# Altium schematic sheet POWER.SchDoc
size A4
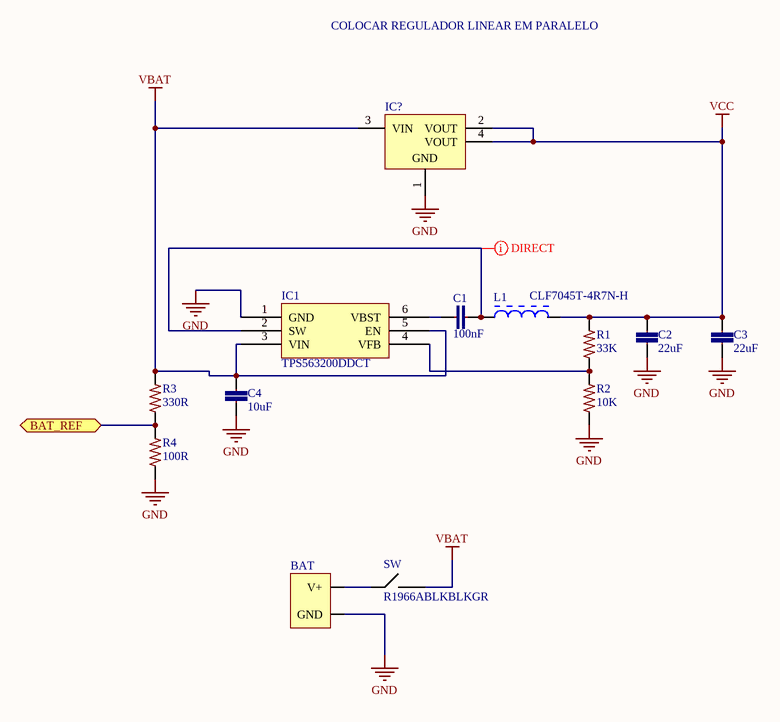
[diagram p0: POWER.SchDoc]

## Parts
BAT  XT60  [BATTERY_CONECTO-PCB]  (value not drawn)
C1  100nF  [0402-CAP]
C2  22uF  [1206-CAP]
C3  22uF  [1206-CAP]
C4  10uF  [1210-CAP]
IC1  TPS563200DDCT  [SOT95P280X110-6N]
IC?  LD1117S33CTR  [SOT-223_N]  (value not drawn)
L1  CLF7045T-4R7N-H  [CLF7045T]
R1  33K  [0402-RES-HD]
R2  10K  [0402-RES-HD]
R3  330R  [0402-RES-HD]
R4  100R  [0402-RES-HD]
SW  R1966ABLKBLKGR  [R1966AB-PCB]

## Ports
BAT_REF

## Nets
GND: BAT.1(GND) C2.1 C3.1 C4.1 IC1.1(GND) IC?.1(GND) R2.1 R4.1
VBAT: C4.2 IC1.3(VIN) IC1.5(EN) IC?.3(VIN) R3.2 SW.1
VCC: C2.2 C3.2 IC?.2(VOUT) IC?.4(VOUT) L1.2 R1.2
BAT_REF: R3.1 R4.2 ; port BAT_REF
NetBAT_0: BAT.0(V+) SW.0
NetC1_1: C1.1 IC1.6(VBST)
NetC1_2: C1.2 IC1.2(SW) L1.1
NetIC1_4: IC1.4(VFB) R1.1 R2.2

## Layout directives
net class DIRECT: NetC1_2

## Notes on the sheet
- COLOCAR REGULADOR LINEAR EM PARALELO

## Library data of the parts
BAT = BATTERY_CONNECTOR: XT60 PRT-10474
C1 = CC0402-100nF-50v-A.3: CAP CER 0.1UF 50V 10% X7R 0402; Part No: C1005X7R1H104K050BB; Value: 100n; Cod EMS: 05.281.019.021
C2 C3 = CC1206-22uF-6.3V-1: CAP CER 22UF 6.3V 20% X5R 1206; Part No: C3216X5R0J226M085AC; Value: 22u; Rule: UNIONINDEX{}0[]RULEKIND{}PolygonConnect[]NETSCOPE{}AnyNet[]LAYERKIND{}SameLayer[]NAME{}Schematic Polygon Connect Style[]CONNECTSTYLE{}Direct[]RELIEFCONDUCTORWIDTH{}10mil[]RELIEFENTRIES{}4[]POLYGONRELIEFANGLE{}45 Angle[]AIRGAPWIDTH{}10mil[]UNIT{}Imperial[]PcbType{}ProtelPcb
C4 = CC1210-10uF-6: CAP CER 10UF 50V 20% X5R 1210; Part No: UMK325BJ106MM; value: 10u; Cod EMS: 05.281.019.522
IC1 = TPS563200DDCT-01.A.2: IC REG BUCK ADJ 3A SYNC 6SOT
IC? = CMP-0244-00307-1: Fixed Low Drop Positive Voltage Regulator, 3.3V, 4-Pin SOT-223, Tape and Reel
L1 = CLF7045T-4R7N-H-2: FIXED IND 4.7UH 4.1A 20 MOHM SMD; Family Description: INDUTORES FIXOS 7,2x6,9mm TDK CLF7045T -45 A 125oC; Rule: UNIONINDEX{}0[]RULEKIND{}PolygonConnect[]NETSCOPE{}AnyNet[]LAYERKIND{}SameLayer[]NAME{}Schematic Polygon Connect Style[]CONNECTSTYLE{}Direct[]RELIEFCONDUCTORWIDTH{}10mil[]RELIEFENTRIES{}4[]POLYGONRELIEFANGLE{}45 Angle[]AIRGAPWIDTH{}10mil[]UNIT{}Imperial[]PcbType{}ProtelPcb
R1 = R0402-33K-7: RES 33K OHM 1/10W 1% 0402 SMD; Part No: ERJ-2RKF3302X; Family Description: RESISTOR FILME ESPESSO 10R-1M / 1/10W / 1% / 0402. P/N: ERJ-2RKF....X – PANASONIC ELECTRONIC COMPONENTS.; Cod EMS: 05.280.029.535
R2 = R0402-10K-10: RES 10K OHM 1/10W 1% 0402 SMD; Part No: ERJ-2RKF1002X; Cod EMS: 05.280.029.525; Family Description: RESISTOR FILME ESPESSO 10R-1M / 1/10W / 1% / 0402. P/N: ERJ-2RKF....X – PANASONIC ELECTRONIC COMPONENTS.
R3 = R0402-10K-10: RES 330R OHM 1/10W 1% 0402 SMD; Part No: ERJ-2RKF1002X; Cod EMS: 05.280.029.525; Value: 330; Family Description: RESISTOR FILME ESPESSO 10R-1M / 1/10W / 1% / 0402. P/N: ERJ-2RKF....X – PANASONIC ELECTRONIC COMPONENTS.
R4 = R0402-33K-7: RES 100R OHM 1/10W 1% 0402 SMD; Part No: ERJ-2RKF3302X; Cod EMS: 05.280.029.535; Value: 100; Family Description: RESISTOR FILME ESPESSO 10R-1M / 1/10W / 1% / 0402. P/N: ERJ-2RKF....X – PANASONIC ELECTRONIC COMPONENTS.
SW = Rocker Switch: SWITCH ROCKER SPST 15A 125V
